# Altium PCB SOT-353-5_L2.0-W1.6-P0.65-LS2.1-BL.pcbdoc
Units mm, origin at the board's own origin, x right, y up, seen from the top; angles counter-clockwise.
Board outline 15.15 x 15.1 mm, 2 copper layers (Top Layer, Bottom Layer), stack 0 mm thick; 1 components, 0 nets, 5 pads, 0 vias.
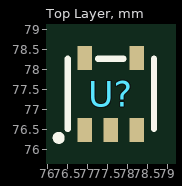
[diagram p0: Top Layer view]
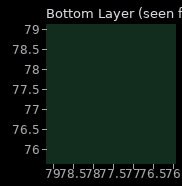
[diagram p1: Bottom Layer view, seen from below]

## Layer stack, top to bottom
Top Layer: signal copper (thickness not stored)
Bottom Layer: signal copper (thickness not stored)

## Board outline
85.004,69.85 69.85,69.85 69.85,84.95 85.004,84.95

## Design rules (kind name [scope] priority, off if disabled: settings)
PasteMaskExpansion "Paste Mask Expansion" [All] p1: expansion=0
SolderMaskExpansion "Solder Mask Expansion" [IsVia] p1: expansion=-25.4 istentingtop=TRUE
SolderMaskExpansion "Solder Mask Expansion" [All] p2: expansion=0.051 istentingtop=FALSE

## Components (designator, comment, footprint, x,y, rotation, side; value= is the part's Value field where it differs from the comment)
U? "" SOT-353-5_L2.0-W1.6-P0.65-LS2.1-BL 77.577,77.4 r0 top

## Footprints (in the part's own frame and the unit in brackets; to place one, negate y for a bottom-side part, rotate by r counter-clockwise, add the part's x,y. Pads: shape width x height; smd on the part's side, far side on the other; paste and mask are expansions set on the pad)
SOT-353-5_L2.0-W1.6-P0.65-LS2.1-BL [mm]
  rect 0.364x0.6 smd: 1(-0.65,-0.9) 2(0,-0.9) 3(0.65,-0.9) 4(0.65,0.9) 5(-0.65,0.9)
  silkscreen extent -1.38,-1.18 1.08,0.88

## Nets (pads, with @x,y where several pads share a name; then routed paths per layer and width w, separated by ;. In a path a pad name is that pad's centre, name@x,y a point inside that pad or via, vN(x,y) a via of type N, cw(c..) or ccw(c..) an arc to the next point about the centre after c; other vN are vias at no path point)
pads on no net: U?.1 U?.2 U?.3 U?.4 U?.5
